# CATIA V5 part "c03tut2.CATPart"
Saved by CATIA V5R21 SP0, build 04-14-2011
Part number: c02tut2
Bounding box of the stored display mesh (mm): x 0 to 0, y -39.994 to 149.998, z -39.999 to 39.984
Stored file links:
  D:\CATIA V5R21 E-RESOURCES\CATIA-V5R21\catia-v5r21-prt\c03-catia-v5r21-prt\catia-v5r21-tut-02.CATPart
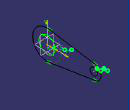
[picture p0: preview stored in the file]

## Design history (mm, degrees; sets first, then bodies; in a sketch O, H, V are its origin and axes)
Body1 (main body)
  Sketch1 on yz-plane, origin (0, 0, 0), H (0, 1, 0), V (0, 0, 1)
    arc A1 centre (0, 0) radius 40 from (6.1538, 39.5238) to (6.1538, -39.5238) ccw
    point P1 (40, 0)
    arc A2 centre (130, 0) radius 20 from (133.0769, -19.7619) to (133.0769, 19.7619) ccw
    point P2 (130, 0)
    line L1 (133.0769, 19.7619) -> (6.1538, 39.5238)
    line L2 (6.1538, -39.5238) -> (133.0769, -19.7619)
    circle A3 centre (0, 0) radius 22.5
    circle A4 centre (130, 0) radius 10
    point P7 (140, 0)
    radius A3 = 22.5
    coincidence: A1 P1, P1 H, P2 H, A4 P7, P7 H
    tangency: L1 A2, L1 A1, L2 A1, L2 A2
    concentricity: A2 A4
